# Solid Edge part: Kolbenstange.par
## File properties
Username: bmolnar
Dokumentum tartalom típus: 0
Author: bmolnar
Last saved by: bmolnar
Revision: 83
Sűrűség: 0,000 kg/m^3
Pontosság: 0,990
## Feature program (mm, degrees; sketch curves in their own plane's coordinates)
base feature "unnamed BaseFeature 1"
sketch for "unnamed Protrusion 1" plane through (54.2, 0.0012, 0) normal (1, 0, 0) x-axis (0, 0, -1)
  circle centre (0, -0.0012) radius 50
extrude "unnamed Protrusion 1" add finite 12.85 along -normal
sketch for "Kihúzás_2" plane through (54.2, 0.0012, 0) normal (1, 0, 0) x-axis (0, 0, -1)
  circle centre (0, -0.0012) radius 50
extrude "Kihúzás_2" add finite 4.3 along +normal
sketch for "Furat_1" plane through (-70, 0.0012, 0) normal (-1, 0, 0) x-axis (0, 0, 1)
  hole centre (0, -0.0012) bore radius 5.053
hole "Furat_1" nominal diameter 12 finite  VBottomAngle = 118 deg; ThreadDepth = 22 mm
chamfer "Letörés_1" setback 1  SetBackValue2 = 45 deg
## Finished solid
Body 1: solid body, 14 faces, 20 edges, 8 vertices.
  Faces by surface: plane 7, cylinder 4, cone 2, torus 1
  Edges by curve: circle 10, line 6, curve on surface 2, ellipse 2
Bounding box of the edges (mm; curved faces can reach further): 128.500 x 100.000 x 100.000, from (-70, -50, -50) to (58.5, 50, 50).
Cylindrical faces by radius (mm): R5.053 x2, R12.5 x1, R50 x1
Conical faces (half-angle, radius in mm at the cone's reference point): 45 deg R6.053 x1, 59 deg R5.053 x1
Toroidal faces (ring radius, tube radius in mm): R10.7 r1.8 x1
Planar faces by outward normal: +x 1, +y 1, -x 2, -y 1, oblique 2
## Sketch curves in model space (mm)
circle centre (54.2, 0, 0) radius 50
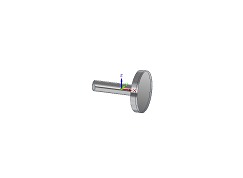
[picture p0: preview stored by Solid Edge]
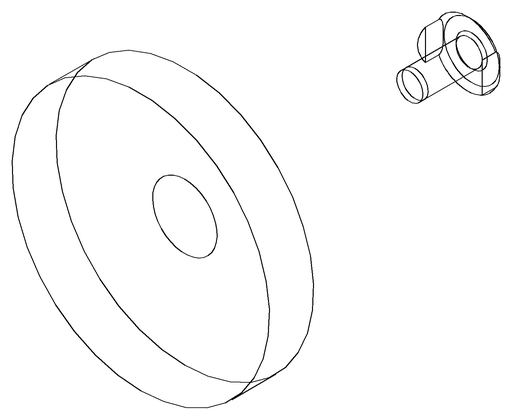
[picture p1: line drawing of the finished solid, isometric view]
